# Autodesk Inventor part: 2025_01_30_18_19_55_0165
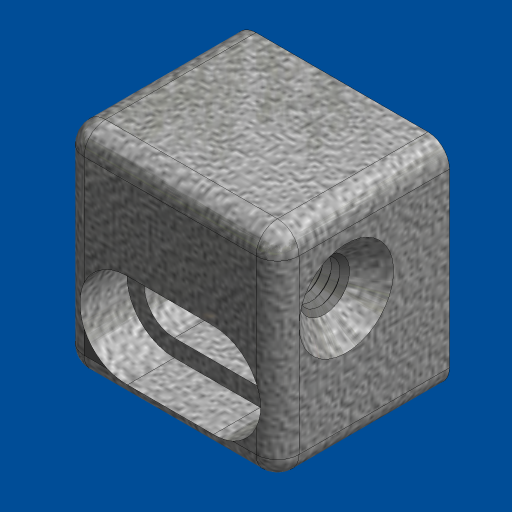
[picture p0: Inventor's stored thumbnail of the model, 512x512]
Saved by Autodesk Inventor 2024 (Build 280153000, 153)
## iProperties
Part Number: 2025_01_30_18_19_55_0165
Material: Aluminum 6061
Description: PART--DESC
Document SubType Name: Modeling
Designer: amoles
Appearance: Aluminum Cast
Mass: 23.8069 g
Surface Area: 42.7269 cm^2
Volume: 8.81737 cm^3
Density: 2.7 g/cm^3
Author: amoles
Revision Number: NONE
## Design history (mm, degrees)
feature "Base1"
body "Solid1"
